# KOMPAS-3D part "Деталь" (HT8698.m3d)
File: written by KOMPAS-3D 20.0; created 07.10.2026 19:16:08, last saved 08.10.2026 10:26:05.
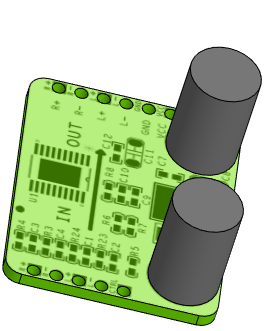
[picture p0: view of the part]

Document properties: Полное имя файла: D:\RicWork\Project-EPS32\box_compas\HT8698.m3d

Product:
- Part/product: Деталь
    Масса: 0.0176922
  - Body: Тело 1
      Масса: 0.0177327

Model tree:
1. Эскиз:1
2. Элемент выдавливания:1
     Расстояние 1 = 1.5
3. Эскиз:2  (with: Элемент выдавливания:1)
4. Элемент выдавливания:2
     Расстояние 1 = 12
5. Эскиз:3  (with: Элемент выдавливания:1)
6. Элемент выдавливания:3
     Расстояние 2 = 1.5
7. Массив по сетке:1  (with: Элемент выдавливания:3, Эскиз:3)  (5 pattern instances)
     Шаг 1 = 10; Угол раствора = -90; Шаг 2 = 2.54
8. Эскиз:4  (with: Элемент выдавливания:1, Элемент выдавливания:3)
9. Элемент выдавливания:4
     Расстояние 2 = 1.5
10. Массив по сетке:2  (with: Элемент выдавливания:4, Эскиз:4)  (6 pattern instances)
     Шаг 1 = 10; Угол раствора = -90; Шаг 2 = 2.54
11. Скругление:1  (with: Элемент выдавливания:1)
     Радиус = 2

Referenced files in D:\RicWork\Project-EPS32\box_compas\: chHT8698.png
